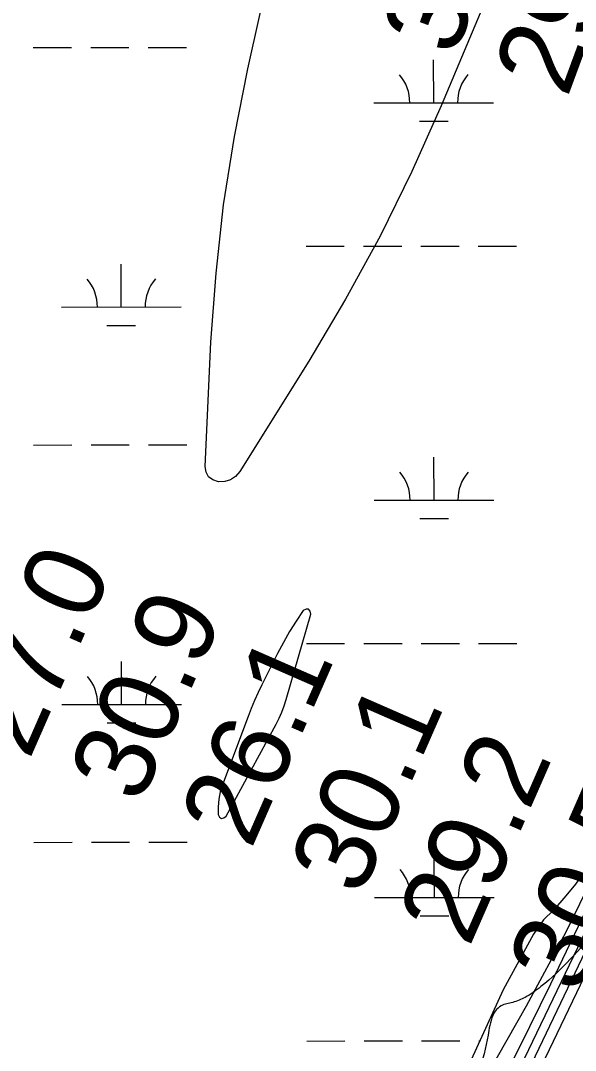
# Model space of a CAD drawing. Extents: x 3297716 to 3335574, y 688621 to 713991.
# Drawn here: x 3319766 to 3320230, y 695242 to 696104 of the extents above; entities that cross this region are included whole.
import ezdxf

# ---------------------------------------------------------------- set-up
doc = ezdxf.new("R2010")
doc.units = 0
for name, color, linetype in [('V-RIVR-EDGE', 7, 'Continuous'), ('V-RIVR-RANG', 7, 'Continuous'), ('V-SITE-VEGE', 7, 'Continuous'), ('V-TOPO-DPTH', 7, 'Continuous'), ('V-TOPO-MAJR', 7, 'Continuous'), ('V-TOPO-MINR', 7, 'Continuous'), ('V-WETL-SWMP', 7, 'Continuous')]:
    doc.layers.add(name, color=color, linetype=linetype)

msp = doc.modelspace()

# ---------------------------------------------------------------- linework, layer by layer
at = {"layer": 'V-RIVR-EDGE'}
msp.add_spline([(3321618.45, 701061.3), (3321639.17, 701040.92), (3321661.92, 701020.55), (3321674.32, 701007.67), (3321694.16, 700986.07), (3321717.72, 700957.41), (3321720.61, 700953.26), (3321724.75, 700950.76), (3321726.82, 700949.51), (3321730.12, 700946.19), (3321742.93, 700927.09), (3321753.65, 700905.93), (3321756.11, 700893.9), (3321759.81, 700884.36), (3321768.06, 700867.34), (3321776.73, 700853.23), (3321786.64, 700837.46), (3321794.49, 700827.9), (3321804.41, 700817.1), (3321812.69, 700810.04), (3321821.8, 700809.18), (3321830.09, 700806.68), (3321833.39, 700803.77), (3321835.87, 700798.79), (3321840.83, 700792.97), (3321849.52, 700787.56), (3321852, 700783.83), (3321866.46, 700765.14), (3321875.54, 700751.02), (3321880.08, 700741.06), (3321885.01, 700725.72), (3321889.55, 700717), (3321895.75, 700710.35), (3321901.94, 700699.15), (3321908.12, 700684.63), (3321912.22, 700664.31), (3321919.16, 700623.67), (3321922, 700598.79), (3321922.33, 700564.8), (3321921.8, 700517.55), (3321919.28, 700502.22), (3321912.99, 700476.13), (3321905.84, 700433.04), (3321899.49, 700379.59), (3321893.61, 700348.1), (3321887.31, 700316.2), (3321880.2, 700288.86), (3321874.74, 700259.03), (3321869.25, 700218.84), (3321863.73, 700164.56), (3321860.77, 700141.35), (3321859.51, 700133.9), (3321857.38, 700109.86), (3321857.72, 700080.85), (3321854.3, 700038.58), (3321847.95, 699987.61), (3321847.83, 699937.46), (3321848.6, 699913.83), (3321849.33, 699873.21), (3321853.78, 699830.51), (3321854.96, 699803.15), (3321853.26, 699786.99), (3321851.54, 699762.54), (3321847.36, 699747.63), (3321844.45, 699743.9), (3321843.17, 699728.57), (3321839.41, 699718.22), (3321831.1, 699708.71), (3321827.36, 699705.81), (3321826.94, 699701.67), (3321826.9, 699687.16), (3321823.15, 699678.88), (3321813.6, 699670.62), (3321798.66, 699664.44), (3321785.76, 699644.16), (3321779.93, 699632.57), (3321773.21, 699598.6), (3321768.1, 699540.58), (3321765.15, 699519.86), (3321762.59, 699492.93), (3321757.53, 699458.54), (3321751.27, 699439.49), (3321741.26, 699415.47), (3321732.08, 699391.04), (3321722.08, 699368.27), (3321716.24, 699354.61), (3321712.46, 699334.72), (3321711.17, 699313.17), (3321708.16, 699269.24), (3321710.2, 699258.88), (3321713.08, 699250.99), (3321718.86, 699240.62), (3321727.54, 699231.89), (3321733.75, 699226.9), (3321735.8, 699219.85), (3321729.5, 699186.29), (3321720.32, 699159.37), (3321709.07, 699134.53), (3321700.31, 699115.49), (3321685.36, 699100.6), (3321679.12, 699094.4), (3321674.96, 699087.37), (3321674.54, 699083.64), (3321670.34, 699063.75), (3321660.32, 699031.86), (3321651.17, 699018.62), (3321638.28, 699002.49), (3321632.02, 698987.58), (3321625.76, 698968.12), (3321619.46, 698936.22), (3321615.66, 698908.04), (3321607.29, 698875.32), (3321593.49, 698825.61), (3321583.49, 698805.33), (3321580.14, 698792.07), (3321580.11, 698777.57), (3321580.08, 698768.03), (3321572.16, 698748.16), (3321567.94, 698717.91), (3321559.1, 698663.64), (3321555.74, 698647.06), (3321554.07, 698638.36), (3321550.73, 698631.74), (3321551.53, 698617.65), (3321548.59, 698601.9), (3321548.13, 698586.15), (3321543.97, 698577.46), (3321538.14, 698566.28), (3321534.37, 698551.37), (3321535.17, 698541.42), (3321533.49, 698532.72), (3321521.4, 698502.08), (3321503.45, 698451.14), (3321490.53, 698421.75), (3321481.38, 698409.33), (3321476.81, 698403.96), (3321474.3, 698395.26), (3321466.79, 698374.55), (3321458.45, 698355.09), (3321454.28, 698343.91), (3321453.02, 698339.36), (3321455.92, 698336.45), (3321456.74, 698333.13), (3321454.65, 698329.4), (3321448.83, 698321.96), (3321440.11, 698313.69), (3321430.98, 698308.32), (3321420.6, 698301.3), (3321418.1, 698296.34), (3321412.68, 698284.33), (3321407.28, 698277.71), (3321395.61, 698252.46), (3321375.16, 698198.21), (3321359.31, 698158.46), (3321345.97, 698126.16), (3321337.19, 698093.85), (3321334.25, 698078.94), (3321334.23, 698070.24), (3321336.69, 698059.45), (3321328.74, 698032.12), (3321314.56, 697996.09), (3321306.62, 697968.76), (3321301.21, 697958.41), (3321293.31, 697951.38), (3321284.15, 697933.99), (3321274.57, 697915.37), (3321271.23, 697904.6), (3321272.45, 697893.82), (3321272.42, 697881.8), (3321266.57, 697862.33), (3321256.95, 697828.37), (3321254.44, 697817.6), (3321249.85, 697808.08), (3321241.51, 697787.79), (3321233.61, 697774.54), (3321226.53, 697762.13), (3321220.27, 697745.56), (3321216.1, 697733.97), (3321215.67, 697727.34), (3321217.73, 697725.67), (3321219.8, 697723.6), (3321219.37, 697718.62), (3321208.12, 697691.71), (3321197.7, 697668.11), (3321194.79, 697666.04), (3321191.06, 697666.05), (3321191.45, 697656.52), (3321188.95, 697651.55), (3321185.63, 697649.07), (3321180.24, 697647.84), (3321181.04, 697635.82), (3321179.37, 697630.85), (3321174.8, 697625.89), (3321172.29, 697619.26), (3321170.2, 697612.22), (3321164.33, 697585.71), (3321162.65, 697577.01), (3321158.92, 697575.78), (3321154.35, 697570.81), (3321148.51, 697557.56), (3321144.77, 697550.53), (3321143.91, 697539.34), (3321140.58, 697535.62), (3321134.77, 697529.41), (3321132.68, 697525.27), (3321128.5, 697509.53), (3321122.64, 697486.75), (3321103.06, 697447.42), (3321100.98, 697441.63), (3321100.95, 697432.92), (3321091.79, 697415.12), (3321084.3, 697404.36), (3321071.4, 697382.01), (3321064.34, 697376.64), (3321056.87, 697372.93), (3321048.14, 697363.42), (3321041.07, 697351), (3321031.9, 697332.37), (3321023.56, 697312.08), (3321015.63, 697288.06), (3321006.43, 697254.51), (3320994.76, 697229.67), (3320983.51, 697207.32), (3320979.36, 697203.6), (3320975.6, 697193.66), (3320968.09, 697172.54), (3320962.64, 697145.61), (3320955.95, 697122.42), (3320943.84, 697086.8), (3320940.48, 697069.4), (3320936.31, 697061.12), (3320926.34, 697048.71), (3320920.93, 697043.34), (3320909.64, 697002.33), (3320899.61, 696969.2), (3320887.51, 696935.24), (3320880.84, 696920.33), (3320879.58, 696912.46), (3320883.28, 696900.43), (3320882.85, 696894.63), (3320876.18, 696878.07), (3320871.56, 696854.04), (3320866.95, 696835.81), (3320859.86, 696815.94), (3320857.35, 696806.82), (3320853.17, 696794.4), (3320849.83, 696784.46), (3320847.3, 696766.64), (3320843.13, 696755.46), (3320836.06, 696746.78), (3320830.23, 696736.43), (3320825.62, 696714.06), (3320819.78, 696699.98), (3320814.39, 696700.82), (3320813.53, 696688.39), (3320798.51, 696648.22), (3320788.51, 696625.45), (3320782.7, 696621.73), (3320776.44, 696606.83), (3320773.11, 696599.38), (3320766.05, 696592.76), (3320752.32, 696573.31), (3320739.41, 696550.14), (3320720.25, 696512.05), (3320700.68, 696473.55), (3320668.58, 696401.51), (3320646.49, 696351.83), (3320619.82, 696291.38), (3320606.9, 696264.05), (3320587.72, 696216.85), (3320576.88, 696191.59), (3320559.79, 696152.26), (3320552.68, 696128.24), (3320546.41, 696106.29), (3320536.39, 696076.47), (3320526.77, 696040.43), (3320506.73, 695984.11), (3320462.47, 695850.34), (3320450.34, 695806.02), (3320441.99, 695784.08), (3320420.24, 695702.06), (3320413.95, 695672.23), (3320409.31, 695639.92), (3320408.02, 695624.17), (3320406.74, 695608.42), (3320408.37, 695594.32), (3320410.83, 695583.96), (3320416.18, 695571.92), (3320421.98, 695567.35), (3320430.26, 695563.18), (3320436.88, 695558.19), (3320439.76, 695552.38), (3320445.95, 695539.93), (3320448.82, 695529.15), (3320449.62, 695514.64), (3320448.35, 695507.18), (3320445.85, 695499.32), (3320439.61, 695490.63), (3320432.95, 695478.62), (3320425.04, 695464.14), (3320423.36, 695454.61), (3320416.68, 695438.87), (3320407.94, 695423.56), (3320400.05, 695416.95), (3320392.16, 695411.99), (3320377.64, 695405.4), (3320369.77, 695408.32), (3320357.76, 695410.42), (3320346.57, 695411.28), (3320320.43, 695400.15), (3320298.01, 695386.53), (3320249, 695343.13), (3320201.63, 695295.58), (3320188.34, 695286.49), (3320177.97, 695282.37), (3320168.43, 695279.5), (3320163.44, 695274.95), (3320158.02, 695258.8), (3320150.48, 695228.14), (3320140.07, 695207.45), (3320125.48, 695174.32), (3320115.05, 695149.48), (3320110.04, 695134.99), (3320108.37, 695129.6), (3320108.36, 695125.87), (3320112.48, 695115.91), (3320113.71, 695108.45), (3320113.28, 695102.65), (3320106.62, 695091.47), (3320104.12, 695086.92), (3320100.38, 695081.54), (3320098.3, 695077.82), (3320098.29, 695074.91), (3320104.89, 695063.71), (3320105.7, 695055.41), (3320108.15, 695041.32), (3320112.69, 695030.11), (3320122.19, 695016.41), (3320128.39, 695010.18), (3320133.76, 695004.36), (3320135.82, 694999.39), (3320135.81, 694993.17), (3320132.46, 694981.16), (3320110.39, 694941.42), (3320095, 694917.83), (3320080.04, 694902.95), (3320068.41, 694893.44), (3320055.95, 694881.45), (3320033.07, 694848.77), (3319991.89, 694787.94), (3319966.93, 694752.36), (3319939.88, 694710.15), (3319919.91, 694678.69), (3319900.35, 694647.24), (3319884.95, 694618.27), (3319831.21, 694511.88), (3319802.89, 694453.92), (3319782.47, 694411.28), (3319716.3, 694301.19), (3319680.91, 694240.35), (3319651.35, 694187.37), (3319580.16, 694059.05), (3319556.78, 694017.46)], degree=3, dxfattribs=at)
at = {"layer": 'V-SITE-VEGE'}
for p, q in [((3320230.43, 695381.38), (3320222.42, 695371.57)), ((3320222.42, 695371.57), (3320212.03, 695359.57)), ((3320212.03, 695359.57), (3320203.64, 695351.41)), ((3320203.64, 695351.41), (3320195.34, 695339.54)), ((3320195.34, 695339.54), (3320170.13, 695292.71)), ((3320170.13, 695292.71), (3320143.17, 695234.34))]:
    msp.add_line(p, q, dxfattribs=at)
at = {"layer": 'V-TOPO-DPTH'}
msp.add_lwpolyline([(3320521.59, 696113.45), (3320507.09, 696075.77), (3320504.76, 696069.5), (3320502.51, 696063.21), (3320500.4, 696056.87), (3320498.38, 696050.49), (3320480.75, 695992.8), (3320469.75, 695957.63), (3320458.45, 695922.56), (3320446.69, 695887.65), (3320434.63, 695852.83), (3320283.01, 695424.16), (3320278.43, 695411.84), (3320273.6, 695399.64), (3320268.38, 695387.59), (3320262.9, 695375.65), (3320100.76, 695036.46)], dxfattribs=at)
at = {"layer": 'V-TOPO-MAJR'}
for points in [[(3320462.07, 696115.05), (3320450.88, 696082.14), (3320440.51, 696048.96), (3320430.69, 696015.6), (3320295.59, 695534.6), (3320289.4, 695513.28), (3320282.97, 695492.04), (3320276.18, 695470.91), (3320269.14, 695449.86), (3320256.31, 695412.58), (3320254.56, 695407.93), (3320252.53, 695403.39), (3320233.79, 695364.49), (3320223.13, 695342.91), (3320212.17, 695321.48), (3320200.79, 695300.27), (3320189.11, 695279.22), (3319865.6, 694709.41)], [(3319932.07, 695452.34), (3319931.52, 695446.07), (3319931.49, 695439.71), (3319932.8, 695437.52), (3319934.35, 695436.36), (3319936.23, 695436.75), (3319938.35, 695438.19), (3319980, 695515.17), (3319982.51, 695520.18), (3319984.8, 695525.29), (3319986.75, 695530.53), (3319988.48, 695535.87), (3320009.15, 695607.25), (3320008.47, 695609.88), (3320007.28, 695611.44), (3320005.32, 695611.4), (3320002.85, 695610.29), (3319996.99, 695601.62), (3319991.4, 695592.78), (3319986.22, 695583.69), (3319981.32, 695574.44), (3319968.23, 695548.31), (3319965.09, 695541.78), (3319962.09, 695535.18), (3319959.3, 695528.5), (3319956.65, 695521.75), (3319935.25, 695464.58), (3319933.4, 695458.5), (3319932.07, 695452.34)]]:
    msp.add_lwpolyline(points, dxfattribs=at)
at = {"layer": 'V-TOPO-MINR'}
for points in [[(3319936.03, 695950.15), (3319945.2, 696007.15), (3319956.35, 696063.9), (3319986.36, 696198.23)], [(3320531.03, 696190.14), (3320496.23, 696099.68), (3320490.64, 696084.64), (3320485.3, 696069.51), (3320480.31, 696054.26), (3320475.57, 696038.93), (3320438.69, 695914.5), (3320415.13, 695837.07), (3320390.82, 695759.89), (3320365.39, 695683.06), (3320339.21, 695606.48), (3320274.06, 695420.31), (3320270.74, 695411.32), (3320267.23, 695402.41), (3320263.43, 695393.61), (3320259.43, 695384.9), (3320184.28, 695228.11)], [(3320163.4, 696140.6), (3320118.27, 696032.94), (3320093.62, 695977.92), (3320067.23, 695923.8), (3320038.24, 695871.02), (3320007.52, 695819.14), (3319949.72, 695726.72), (3319946.11, 695722.74), (3319942, 695719.79), (3319937.13, 695718.4), (3319931.77, 695718.04), (3319927.17, 695719.76), (3319923.61, 695722.36), (3319921.6, 695726.29), (3319920.62, 695731.1), (3319925.57, 695835.08), (3319929.82, 695892.74), (3319936.03, 695950.15)], [(3320485.16, 696123.68), (3320476.43, 696099.82), (3320468.09, 696075.82), (3320460.36, 696051.63), (3320453.02, 696027.3), (3320366.34, 695726.53), (3320350.3, 695672.48), (3320333.68, 695618.61), (3320316.21, 695565.01), (3320298.16, 695511.6), (3320265.16, 695416.45), (3320263.09, 695410.79), (3320260.89, 695405.17), (3320258.5, 695399.64), (3320255.97, 695394.15), (3320209.6, 695297.63), (3320183.25, 695244.21), (3320156.18, 695191.17)], [(3320558.54, 696114.91), (3320544.23, 696084.02), (3320530.48, 696052.89), (3320517.59, 696021.39), (3320505.27, 695989.65), (3320493.35, 695957.74), (3320481.41, 695925.84), (3320469.45, 695893.95), (3320457.45, 695862.06), (3320294.14, 695428.47), (3320287.82, 695412.34), (3320281.23, 695396.32), (3320274.22, 695380.48), (3320266.94, 695364.76), (3320003.63, 694814.92)], [(3320521.59, 696113.45), (3320507.09, 696075.77), (3320504.76, 696069.5), (3320502.51, 696063.21), (3320500.4, 696056.87), (3320498.38, 696050.49), (3320480.75, 695992.8), (3320469.75, 695957.63), (3320458.45, 695922.56), (3320446.69, 695887.65), (3320434.63, 695852.83), (3320283.01, 695424.16), (3320278.43, 695411.84), (3320273.6, 695399.64), (3320268.38, 695387.59), (3320262.9, 695375.65), (3320100.76, 695036.46)]]:
    msp.add_lwpolyline(points, dxfattribs=at)
at = {"layer": 'V-WETL-SWMP'}
for p, q in [((3319777, 696081.65), (3319809, 696081.67)), ((3319825, 696081.69), (3319857, 696081.71)), ((3319873, 696081.73), (3319905, 696081.75)), ((3320111.88, 696035.5), (3320111.85, 696071.5)), ((3320061.88, 696035.46), (3320161.88, 696035.54)), ((3320099.89, 696020.06), (3320123.89, 696020.08)), ((3320005.14, 695915.34), (3320037.14, 695915.36)), ((3320053.14, 695915.38), (3320085.14, 695915.4)), ((3320101.14, 695915.42), (3320133.14, 695915.45)), ((3320149.14, 695915.46), (3320181.14, 695915.49)), ((3319850.59, 695864.47), (3319850.56, 695900.47)), ((3319800.59, 695864.42), (3319900.59, 695864.51)), ((3319838.6, 695849.03), (3319862.6, 695849.05)), ((3319777.28, 695748.97), (3319809.28, 695749)), ((3319825.28, 695749.01), (3319857.28, 695749.04)), ((3319873.28, 695749.05), (3319905.28, 695749.08)), ((3320112.16, 695702.82), (3320112.13, 695738.82)), ((3320062.16, 695702.78), (3320162.16, 695702.87)), ((3320100.17, 695687.38), (3320124.17, 695687.4)), ((3320005.41, 695582.66), (3320037.41, 695582.69)), ((3320053.41, 695582.7), (3320085.41, 695582.73)), ((3320101.41, 695582.74), (3320133.41, 695582.77)), ((3320149.41, 695582.78), (3320181.41, 695582.81)), ((3319850.87, 695531.79), (3319850.84, 695567.79)), ((3319800.87, 695531.75), (3319900.87, 695531.83)), ((3319838.88, 695516.35), (3319862.88, 695516.37)), ((3319777.55, 695416.3), (3319809.55, 695416.33)), ((3319825.55, 695416.34), (3319857.55, 695416.37)), ((3319873.55, 695416.38), (3319905.55, 695416.41)), ((3320112.43, 695370.15), (3320112.4, 695406.15)), ((3320230.4, 695381.39), (3320222.38, 695371.58)), ((3320233.07, 695384.89), (3320230.4, 695381.39)), ((3320062.43, 695370.11), (3320162.43, 695370.19)), ((3320222.38, 695371.58), (3320212, 695359.58)), ((3320100.45, 695354.71), (3320124.45, 695354.73)), ((3320212, 695359.58), (3320203.61, 695351.43)), ((3320203.61, 695351.43), (3320195.31, 695339.55)), ((3320195.31, 695339.55), (3320170.1, 695292.72)), ((3320170.1, 695292.72), (3320143.14, 695234.36)), ((3320005.69, 695249.99), (3320037.69, 695250.02)), ((3320053.69, 695250.03), (3320085.69, 695250.06)), ((3320101.69, 695250.07), (3320133.69, 695250.1)), ((3320149.69, 695250.11), (3320150.42, 695250.11))]:
    msp.add_line(p, q, dxfattribs=at)
for centre, start, end in [((3320056.64, 696035.93), 359.27624, 40.81989), ((3320167.12, 696036.02), 139.27624, 180.8199), ((3319795.35, 695864.89), 359.27624, 40.81989), ((3319905.83, 695864.99), 139.27624, 180.8199), ((3320056.91, 695703.25), 359.27624, 40.81989), ((3320167.4, 695703.34), 139.27624, 180.8199), ((3319795.62, 695532.22), 359.27624, 40.81989), ((3319906.11, 695532.31), 139.27624, 180.8199), ((3320057.19, 695370.58), 359.27624, 40.81989), ((3320167.68, 695370.67), 139.27624, 180.8199)]:
    msp.add_arc(centre, 35.25, start, end, dxfattribs=at)

# ---------------------------------------------------------------- texts
at = {"layer": 'V-RIVR-RANG'}
for s, rotation, p in [('36.9', 69.76833, (3320129.47, 696072.87)), ('29.7', 69.76833, (3320223.48, 696038.77)), ('27.0', 66.34833, (3319773.55, 695484.52)), ('30.9', 66.34833, (3319866.3, 695447.04)), ('26.1', 66.34833, (3319959.06, 695409.56)), ('30.1', 66.34833, (3320050.75, 695369.66)), ('29.2', 66.34833, (3320141.5, 695327.59)), ('30.5', 66.34833, (3320233.19, 695287.69))]:
    msp.add_text(s, height=67, rotation=rotation, dxfattribs=at).set_placement(p)

doc.saveas('drawing.dxf')
